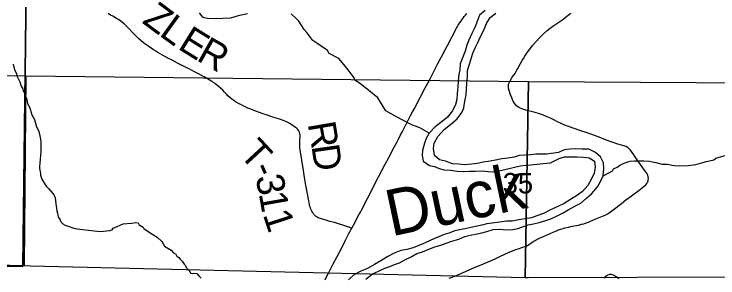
# Model space of a CAD drawing. Extents: x 0 to 34, y -8.9 to 22.
# Drawn here: x 26.101 to 27.543, y 15.913 to 16.454 of the extents above; entities that cross this region are included whole.
import ezdxf

# ---------------------------------------------------------------- set-up
doc = ezdxf.new("R2010")
doc.units = 0
for name, color, linetype in [('GM_X_Corporation', 7, 'Continuous'), ('GM_X_Major_River', 7, 'Continuous'), ('GM_X_Major_River_Text', 7, 'Continuous'), ('GM_X_Minor_River', 7, 'Continuous'), ('GM_X_Section_Text', 7, 'Continuous'), ('GM_X_State_Route', 7, 'Continuous'), ('GM_X_Township_Road', 7, 'Continuous'), ('GM_X_Township_Road_Text', 7, 'Continuous')]:
    doc.layers.add(name, color=color, linetype=linetype)

msp = doc.modelspace()

# ---------------------------------------------------------------- linework, layer by layer
at = {"layer": 'GM_X_Corporation'}
for points in [[(23.7167, 19.34), (23.7167, 15.9913), (24.0651, 15.9828), (24.2771, 15.9807), (24.8268, 15.964), (25.6785, 15.9418), (25.7922, 15.939), (26.1186, 15.9366), (26.135, 17.3055), (26.1361, 17.3278), (26.1391, 17.8847), (26.1399, 18.3037), (25.7381, 18.312), (25.2083, 18.3108), (25.1045, 18.3117), (25.1124, 18.5932), (25.1216, 18.6194), (25.125, 18.6354), (25.1229, 18.6966), (25.1136, 18.8385), (25.1068, 18.8675), (25.1066, 19.3232), (25.0504, 19.3237), (24.5181, 19.3295)], [(23.7167, 15.9913), (23.7167, 14.6), (28.1739, 14.6), (28.1809, 15.2987), (28.1918, 16.1509), (28.1846, 16.3341), (28.1817, 16.6637), (28.1928, 16.8054), (28.1882, 17.3108), (27.911, 17.3104), (27.4798, 17.3159), (27.0561, 17.3117), (26.7292, 17.3169), (26.394, 17.3229), (26.1361, 17.3278), (26.135, 17.3055), (26.1186, 15.9366), (25.7922, 15.939), (25.6785, 15.9418), (24.8268, 15.964), (24.2771, 15.9807), (24.0651, 15.9828)], [(25.0882, 16.3389), (26.1244, 16.3272), (26.121, 15.938), (25.6533, 15.9488), (25.159, 15.9613), (25.0869, 15.9626)], [(26.1244, 16.3272), (27.1548, 16.3158), (27.1478, 15.9137), (26.1339, 15.9374), (26.121, 15.938)], [(27.1548, 16.3158), (28.186, 16.3096), (28.1824, 15.9226), (27.6011, 15.915), (27.1541, 15.9136), (27.1478, 15.9137)]]:
    msp.add_lwpolyline(points, close=True, dxfattribs=at)
at = {"layer": 'GM_X_Major_River'}
for points in [[(27.0659, 16.4614), (27.0539, 16.4514), (27.0499, 16.4407), (27.0447, 16.4266), (27.0388, 16.4144), (27.0326, 16.4003), (27.0286, 16.3904), (27.0249, 16.3778), (27.0209, 16.3675), (27.0143, 16.3522), (27.0141, 16.3397), (27.0119, 16.3298), (27.0106, 16.3169), (27.0096, 16.3048), (27.0083, 16.2915), (27.0077, 16.2786), (27.0052, 16.2687), (26.9989, 16.2557), (26.9885, 16.243), (26.978, 16.2338), (26.9634, 16.2226), (26.9514, 16.2099), (26.9447, 16.1992), (26.9414, 16.1897), (26.9375, 16.1741), (26.9368, 16.1646), (26.9389, 16.1525), (26.9515, 16.1439), (26.9618, 16.1414), (26.9717, 16.1377), (26.982, 16.1345), (26.9945, 16.1343), (27.0086, 16.1322), (27.0222, 16.1312), (27.0336, 16.1318), (27.0453, 16.1319), (27.0594, 16.1329), (27.0719, 16.1311), (27.0825, 16.1305), (27.0976, 16.1334), (27.1233, 16.1398), (27.1373, 16.143), (27.1491, 16.1443), (27.1589, 16.1452), (27.1725, 16.1465), (27.185, 16.1475), (27.1994, 16.1492), (27.2173, 16.1581)], [(27.216, 16.1706), (27.1916, 16.1669), (27.1696, 16.1666), (27.1594, 16.1653), (27.1473, 16.1652), (27.1355, 16.1639), (27.1253, 16.1611), (27.1121, 16.159), (27.1003, 16.1573), (27.0867, 16.1545), (27.072, 16.1516), (27.0618, 16.1503), (27.0504, 16.1479), (27.0376, 16.1466), (27.0243, 16.1453), (27.0114, 16.1462), (26.9989, 16.1468), (26.9844, 16.1523), (26.9722, 16.1556), (26.9619, 16.1645), (26.9602, 16.1782), (26.9615, 16.1892), (26.9689, 16.2033), (26.9816, 16.2175), (26.9948, 16.2276), (27.0086, 16.2395), (27.0183, 16.2525), (27.022, 16.2621), (27.0241, 16.2754), (27.0269, 16.2883), (27.0279, 16.3005), (27.0281, 16.3126), (27.0294, 16.3263), (27.0296, 16.3384), (27.0333, 16.3491), (27.0365, 16.3601), (27.0405, 16.3738), (27.0461, 16.386), (27.0505, 16.3956), (27.056, 16.4078), (27.0634, 16.4212), (27.0689, 16.4349), (27.0759, 16.4467), (27.0876, 16.456)], [(27.215, 16.0415), (27.2255, 16.047), (27.2357, 16.0528), (27.2493, 16.0601), (27.2622, 16.0667), (27.2734, 16.0767), (27.2847, 16.0863), (27.296, 16.0997), (27.3012, 16.1096), (27.3075, 16.1226), (27.3089, 16.1366), (27.3084, 16.1491), (27.3022, 16.1616), (27.2919, 16.1706), (27.2786, 16.1769), (27.2649, 16.1772), (27.2516, 16.1778), (27.2395, 16.1773), (27.2277, 16.1757), (27.216, 16.1706)], [(27.2173, 16.1581), (27.2286, 16.1617), (27.2419, 16.1614), (27.2544, 16.1615), (27.2674, 16.1605), (27.2791, 16.1595), (27.2902, 16.1524), (27.2911, 16.1406), (27.2889, 16.1277), (27.283, 16.1151), (27.2759, 16.1025), (27.265, 16.0906), (27.2548, 16.0829), (27.2408, 16.0737), (27.228, 16.066), (27.2159, 16.0605)], [(27.2159, 16.0605), (27.1984, 16.0524), (27.1853, 16.0454), (27.1717, 16.0407), (27.1611, 16.0368), (27.1346, 16.0326), (27.1214, 16.0294), (27.1093, 16.0296), (27.0957, 16.0279), (27.0692, 16.0245), (27.0593, 16.0217), (27.0495, 16.0193), (27.0367, 16.0169), (27.0242, 16.0141), (27.0136, 16.012), (27.0034, 16.0096), (26.9913, 16.0053), (26.9815, 16.0025), (26.9544, 15.9907), (26.9412, 15.9849), (26.9314, 15.9806), (26.9186, 15.9751), (26.905, 15.9715), (26.8929, 15.9698), (26.8793, 15.9643), (26.8665, 15.9573), (26.8522, 15.9484), (26.839, 15.941), (26.8247, 15.9325), (26.8112, 15.927), (26.7969, 15.9196), (26.786, 15.9092)], [(26.8216, 15.9108), (26.8348, 15.9216), (26.8472, 15.9274), (26.86, 15.9337), (26.8702, 15.9369), (26.88, 15.9408), (26.8902, 15.9443), (26.9015, 15.9506), (26.9139, 15.9568), (26.9259, 15.9634), (26.9373, 15.967), (26.9505, 15.9721), (26.9625, 15.9768), (26.975, 15.9808), (26.9859, 15.9843), (26.9976, 15.989), (27.012, 15.993), (27.024, 15.9981), (27.035, 16.0009), (27.0494, 16.0034), (27.0592, 16.0058), (27.069, 16.0086), (27.0822, 16.0129), (27.0959, 16.0131), (27.1099, 16.0118), (27.1228, 16.0127), (27.1326, 16.0144), (27.1424, 16.0183), (27.1541, 16.0223), (27.1651, 16.0243), (27.1768, 16.0271), (27.1904, 16.0307), (27.2006, 16.0346), (27.215, 16.0415)]]:
    msp.add_lwpolyline(points, dxfattribs=at)
at = {"layer": 'GM_X_Minor_River'}
for points in [[(26.5788, 16.4546), (26.5595, 16.4501), (26.544, 16.4457), (26.5126, 16.444), (26.4966, 16.4449), (26.4901, 16.446), (26.4871, 16.4478), (26.4805, 16.4565)], [(26.9514, 16.2099), (26.9317, 16.2208), (26.9233, 16.2241), (26.9184, 16.2259), (26.8961, 16.237), (26.8843, 16.2432), (26.8624, 16.2554), (26.846, 16.2821), (26.8348, 16.2911), (26.8102, 16.3112), (26.7987, 16.3183), (26.7971, 16.3232), (26.787, 16.3371), (26.7827, 16.3431), (26.766, 16.3629), (26.7465, 16.3729), (26.743, 16.3793), (26.7211, 16.3941), (26.7126, 16.3997), (26.7002, 16.4159), (26.6948, 16.4222), (26.6839, 16.4392), (26.6784, 16.4448), (26.668, 16.4541)], [(26.0985, 16.3516), (26.1013, 16.3395), (26.1056, 16.3324), (26.1065, 16.3271), (26.112, 16.315), (26.1148, 16.3063), (26.1179, 16.3018), (26.12, 16.2954), (26.1223, 16.292), (26.1235, 16.2863), (26.1259, 16.2814), (26.1283, 16.2708), (26.1327, 16.2621), (26.1367, 16.2474), (26.1426, 16.238), (26.1466, 16.2232), (26.1513, 16.2142), (26.1538, 16.2013), (26.1555, 16.193), (26.1556, 16.1873), (26.1555, 16.1717), (26.1545, 16.1652), (26.1532, 16.1485), (26.1526, 16.1416), (26.1527, 16.1375), (26.1547, 16.1276), (26.1548, 16.1242), (26.1576, 16.1159), (26.1596, 16.1121), (26.1662, 16.1012), (26.1708, 16.0967), (26.1801, 16.0862), (26.1821, 16.0836), (26.1836, 16.081), (26.1845, 16.0775), (26.1858, 16.065), (26.1866, 16.0612), (26.188, 16.0506), (26.1896, 16.0461), (26.1912, 16.0381), (26.1947, 16.0329), (26.1951, 16.0302), (26.2006, 16.0239), (26.2052, 16.0213), (26.2247, 16.0144), (26.241, 16.0127), (26.2768, 16.0087), (26.2968, 16.0106), (26.3018, 16.0121)], [(27.3075, 16.1226), (27.3191, 16.1288), (27.3266, 16.1331), (27.3285, 16.1369), (27.336, 16.1401), (27.3412, 16.1436), (27.3472, 16.1471), (27.3585, 16.1511), (27.3627, 16.1524), (27.3717, 16.1533), (27.3907, 16.1532), (27.4028, 16.1523), (27.4085, 16.1509), (27.4153, 16.1499), (27.4283, 16.1467), (27.4396, 16.1465), (27.4488, 16.1441), (27.4537, 16.1434), (27.4636, 16.1432), (27.4825, 16.1435), (27.4976, 16.1457), (27.5119, 16.1501), (27.5195, 16.1522), (27.5345, 16.1555), (27.5387, 16.1589), (27.5598, 16.165)], [(26.3018, 16.0121), (26.3036, 16.0156), (26.3115, 16.0188), (26.3243, 16.0243), (26.3414, 16.0257), (26.3501, 16.0266), (26.3547, 16.0263), (26.357, 16.0218), (26.3651, 16.0173), (26.3666, 16.0143), (26.3793, 16.0058), (26.3847, 16.0024), (26.3935, 15.9969), (26.4032, 15.9879), (26.4051, 15.9845), (26.409, 15.9785), (26.4221, 15.97), (26.4271, 15.9647), (26.4317, 15.9621), (26.434, 15.958), (26.4383, 15.9554), (26.441, 15.9517), (26.4452, 15.9479), (26.4491, 15.9415), (26.4518, 15.9389), (26.453, 15.9347), (26.4577, 15.9299), (26.4604, 15.9265), (26.462, 15.9231), (26.4658, 15.9224), (26.4711, 15.9229), (26.4753, 15.9226), (26.4792, 15.9177), (26.4838, 15.9132)]]:
    msp.add_lwpolyline(points, dxfattribs=at)
at = {"layer": 'GM_X_State_Route'}
for points in [[(26.9884, 16.3896), (26.9976, 16.4069), (27.0073, 16.425), (27.0091, 16.4282), (27.0108, 16.431), (27.0133, 16.435), (27.0159, 16.4389), (27.0179, 16.4418), (27.0202, 16.4449), (27.0231, 16.4488), (27.0255, 16.4519), (27.0283, 16.4553)], [(26.7377, 15.9097), (26.7409, 15.9158), (26.7446, 15.9232), (26.7487, 15.9313), (26.7538, 15.9409), (26.7624, 15.9571), (26.7719, 15.9752), (26.7789, 15.9891), (26.7867, 16.0046), (26.7893, 16.0095), (26.7904, 16.0117), (26.7923, 16.0151), (26.7999, 16.0292), (26.8037, 16.0363), (26.8072, 16.0428), (26.8101, 16.0483), (26.8122, 16.0522), (26.8162, 16.0598), (26.8198, 16.0671), (26.8253, 16.0775), (26.8476, 16.1205), (26.861, 16.1464), (26.8682, 16.1601), (26.8797, 16.1814), (26.8853, 16.1924), (26.8882, 16.1979), (26.8919, 16.2051), (26.8962, 16.2133), (26.9011, 16.2227), (26.9131, 16.2458), (26.9171, 16.2535), (26.9208, 16.2606), (26.9333, 16.2842), (26.9423, 16.3012), (26.949, 16.3139), (26.9536, 16.3227), (26.9691, 16.3524), (26.9762, 16.3662), (26.9845, 16.3822), (26.9884, 16.3896)]]:
    msp.add_lwpolyline(points, dxfattribs=at)
at = {"layer": 'GM_X_Township_Road'}
for points in [[(26.7923, 16.0151), (26.7844, 16.018), (26.776, 16.0209), (26.7656, 16.0244), (26.7573, 16.0268), (26.7477, 16.0293), (26.7417, 16.031), (26.7322, 16.0337), (26.7281, 16.0351), (26.7257, 16.0359), (26.7236, 16.0367), (26.7217, 16.0378), (26.72, 16.0389), (26.7185, 16.04), (26.7171, 16.0413), (26.7157, 16.0427), (26.7146, 16.0439), (26.7133, 16.0455), (26.7118, 16.0479), (26.7106, 16.05), (26.7089, 16.0539), (26.7078, 16.0568), (26.7069, 16.0598), (26.7061, 16.0628), (26.7042, 16.0713), (26.7015, 16.0859), (26.6979, 16.1066), (26.6959, 16.1188), (26.6937, 16.1335), (26.69, 16.1547), (26.6872, 16.1717), (26.6863, 16.179), (26.686, 16.1845), (26.686, 16.1895), (26.6864, 16.1962), (26.6867, 16.2025), (26.6867, 16.2062), (26.6862, 16.2092), (26.6852, 16.2122), (26.6838, 16.2149), (26.6819, 16.2174), (26.6797, 16.2196), (26.6763, 16.2222), (26.6733, 16.2243), (26.6718, 16.2253), (26.6683, 16.2277), (26.6672, 16.2283), (26.664, 16.2302), (26.6574, 16.2336), (26.6517, 16.2361), (26.6471, 16.2378), (26.6424, 16.2393), (26.6329, 16.2423), (26.6288, 16.2436), (26.6235, 16.2453), (26.6152, 16.2481), (26.6105, 16.2497), (26.6088, 16.2503), (26.6035, 16.252), (26.5936, 16.2556), (26.5855, 16.2589), (26.5798, 16.2614), (26.5698, 16.2662), (26.5653, 16.2685), (26.5631, 16.2696), (26.5544, 16.2744), (26.5507, 16.2766), (26.5466, 16.2793), (26.5423, 16.2829), (26.5388, 16.2864), (26.5355, 16.2901), (26.5318, 16.2942), (26.5284, 16.2978), (26.5229, 16.303), (26.5174, 16.3078), (26.5129, 16.3112), (26.5104, 16.313), (26.5058, 16.3161), (26.5005, 16.3193), (26.4913, 16.3245), (26.4772, 16.3322), (26.469, 16.3366), (26.4591, 16.3417), (26.4558, 16.3434), (26.4519, 16.3453), (26.4436, 16.3495), (26.4408, 16.3509), (26.4353, 16.3536), (26.4242, 16.3592), (26.4159, 16.3634), (26.4045, 16.3698), (26.3954, 16.3752), (26.3912, 16.3778), (26.3865, 16.3808), (26.3767, 16.3874), (26.3666, 16.3946), (26.3607, 16.3991), (26.356, 16.4031), (26.3533, 16.4056), (26.3498, 16.4092), (26.343, 16.4164), (26.3371, 16.4227), (26.3307, 16.4294), (26.3262, 16.4336), (26.3233, 16.4361), (26.3194, 16.4391), (26.3143, 16.4426), (26.3106, 16.4448), (26.3026, 16.4495), (26.2983, 16.452), (26.293, 16.4553)], [(26.9923, 15.9126), (27.0038, 15.9173), (27.021, 15.9245), (27.0437, 15.9347), (27.0621, 15.9423), (27.086, 15.9527), (27.0962, 15.9572), (27.1063, 15.962), (27.1147, 15.966), (27.1204, 15.9685), (27.128, 15.9714), (27.1332, 15.9732), (27.1433, 15.9764), (27.1474, 15.9778), (27.1497, 15.9787), (27.1536, 15.9807), (27.1567, 15.9827), (27.1645, 15.9879), (27.1668, 15.9894), (27.1683, 15.9903), (27.1703, 15.9913), (27.177, 15.9947), (27.1866, 15.999), (27.2054, 16.0072), (27.2088, 16.0087), (27.2121, 16.0101), (27.2141, 16.0109), (27.2162, 16.0118), (27.2183, 16.0125), (27.2203, 16.0131), (27.2234, 16.0142), (27.2291, 16.0157), (27.2363, 16.0176), (27.2443, 16.0192), (27.2571, 16.0217), (27.2631, 16.0232), (27.2679, 16.0245), (27.2726, 16.0261), (27.279, 16.0285), (27.2875, 16.0322), (27.2944, 16.035), (27.2961, 16.0357), (27.306, 16.0396), (27.3116, 16.0421), (27.3165, 16.0447), (27.3217, 16.048), (27.3281, 16.0528), (27.3451, 16.0661), (27.3544, 16.0733), (27.3629, 16.0795), (27.3684, 16.0835), (27.3713, 16.0857), (27.3733, 16.0871), (27.3813, 16.093), (27.3843, 16.0952), (27.3911, 16.1006), (27.3948, 16.104), (27.3971, 16.1068), (27.3987, 16.1095), (27.3996, 16.1118), (27.4001, 16.1142), (27.4003, 16.1173), (27.4001, 16.1204), (27.399, 16.1239), (27.397, 16.1278), (27.3938, 16.1323), (27.3839, 16.1459), (27.3789, 16.153), (27.372, 16.1633), (27.3657, 16.1726), (27.3631, 16.176), (27.3605, 16.1787), (27.3591, 16.1799), (27.3575, 16.1809), (27.3548, 16.1824), (27.352, 16.1836), (27.3472, 16.185), (27.3358, 16.1881), (27.3281, 16.1906), (27.3182, 16.1941), (27.3089, 16.1978), (27.2997, 16.2014), (27.2751, 16.2103), (27.2598, 16.2154), (27.2504, 16.2186), (27.244, 16.2209), (27.2423, 16.2215), (27.237, 16.2233), (27.2323, 16.2249), (27.2243, 16.2283), (27.2204, 16.2302), (27.2143, 16.2332), (27.2066, 16.2372), (27.1999, 16.2405), (27.1932, 16.2436), (27.1857, 16.2466), (27.1775, 16.2494), (27.168, 16.2521), (27.1519, 16.2563), (27.1442, 16.2585), (27.1396, 16.2602), (27.1363, 16.2618), (27.1331, 16.2638), (27.1302, 16.2661), (27.1277, 16.2688), (27.1255, 16.2718), (27.1234, 16.2756), (27.1203, 16.2824), (27.1178, 16.2887), (27.1149, 16.2976), (27.1137, 16.3018), (27.1134, 16.3042), (27.1135, 16.3066), (27.1136, 16.3076), (27.1138, 16.3093), (27.1144, 16.3116), (27.1155, 16.3145), (27.1175, 16.3183), (27.1215, 16.3245), (27.1263, 16.3318), (27.1292, 16.3365), (27.1314, 16.3403), (27.1325, 16.3425), (27.1384, 16.3527), (27.1418, 16.3587), (27.1443, 16.3629), (27.1473, 16.3677), (27.1528, 16.3759), (27.1572, 16.3819), (27.1629, 16.3893), (27.1698, 16.3972), (27.178, 16.4058), (27.1863, 16.4141), (27.1932, 16.4204), (27.199, 16.4251), (27.2065, 16.4305), (27.225, 16.4431), (27.2335, 16.4493), (27.2413, 16.4555)], [(27.3101, 15.913), (27.3115, 15.9151), (27.3131, 15.9169), (27.3151, 15.9184), (27.3173, 15.9196), (27.3196, 15.9205), (27.3214, 15.9208), (27.3239, 15.9208), (27.3257, 15.9205), (27.3281, 15.9198), (27.3309, 15.9184), (27.3332, 15.9168), (27.3361, 15.9146), (27.3394, 15.9112)]]:
    msp.add_lwpolyline(points, dxfattribs=at)

# ---------------------------------------------------------------- texts
at = {"layer": 'GM_X_Major_River_Text'}
msp.add_text('Duck', height=0.0947, rotation=11.9039, dxfattribs=at).set_placement((26.8731, 15.9981))
at = {"layer": 'GM_X_Section_Text'}
msp.add_text('35', height=0.04186, rotation=0, dxfattribs=at).set_placement((27.1018, 16.0865))
at = {"layer": 'GM_X_Township_Road_Text'}
for s, rotation, p in [('Z', 323.387, (26.3611, 16.437)), ('L', 324.2306, (26.3959, 16.4111)), ('E', 328.1119, (26.4339, 16.384)), ('R', 330.5625, (26.4722, 16.3602)), ('R', 279.6587, (26.702, 16.2293)), ('T', 312.7782, (26.5603, 16.1655)), ('D', 278.0992, (26.7098, 16.1837)), ('-', 294.0719, (26.5865, 16.1384)), ('3', 281.2446, (26.595, 16.1203)), ('1', 280.0167, (26.6018, 16.0863)), ('1', 288.2116, (26.61, 16.0432))]:
    msp.add_text(s, height=0.0568, rotation=rotation, dxfattribs=at).set_placement(p)

doc.saveas('drawing.dxf')
